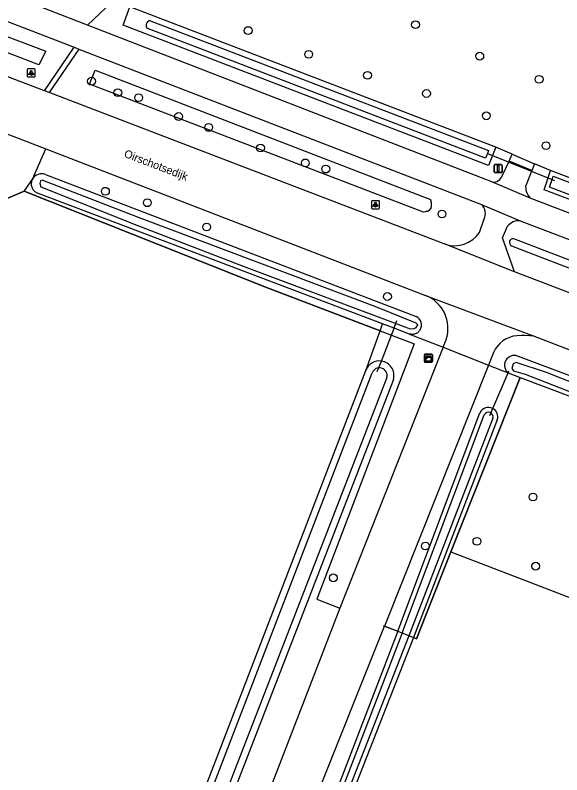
# Model space of a CAD drawing. Extents: x 155209 to 156823, y 385356 to 388482.
# Drawn here: x 155814.6 to 155882.9, y 386615.6 to 386710.5 of the extents above; entities that cross this region are included whole.
import ezdxf

# ---------------------------------------------------------------- set-up
doc = ezdxf.new("R2010")
doc.units = 0
for name, color, linetype in [('IMGEO_Berm_groen', 7, 'Continuous'), ('IMGEO_Boom', 7, 'Continuous'), ('IMGEO_Bouwland', 7, 'Continuous'), ('IMGEO_Duiker', 7, 'Continuous'), ('IMGEO_Erf', 7, 'Continuous'), ('IMGEO_Fietspad_gesloten', 7, 'Continuous'), ('IMGEO_Gemengd_bos', 7, 'Continuous'), ('IMGEO_Grasland_overig', 7, 'Continuous'), ('IMGEO_Groenvoorziening', 7, 'Continuous'), ('IMGEO_Haag', 7, 'Continuous'), ('IMGEO_Hek', 7, 'Continuous'), ('IMGEO_Kast', 7, 'Continuous'), ('IMGEO_Lichtpunt', 7, 'Continuous'), ('IMGEO_Openbare_ruimte_label', 7, 'Continuous'), ('IMGEO_Rijbaan_lokaal_gesloten', 7, 'Continuous'), ('IMGEO_Rijbaan_lokaal_open', 7, 'Continuous'), ('IMGEO_Verkeersbordpaal', 7, 'Continuous'), ('IMGEO_Voetpad_gesloten', 7, 'Continuous'), ('IMGEO_Voetpad_open', 7, 'Continuous'), ('IMGEO_Waterloop', 7, 'Continuous')]:
    doc.layers.add(name, color=color, linetype=linetype)

msp = doc.modelspace()

# ---------------------------------------------------------------- linework, layer by layer
at = {"layer": 'IMGEO_Berm_groen'}
for points in [[(155823.665, 386709.227), (155826.778, 386712.153)], [(155874.621, 386693.991), (155873.73, 386691.681), (155828.114, 386709.2), (155828.929, 386711.51)], [(155876.68, 386693.108), (155874.621, 386693.991)], [(155881.467, 386691.056), (155879.459, 386691.917)], [(155990.993, 386649.297), (155990.059, 386646.729), (155916.515, 386675.029), (155880.657, 386688.651), (155881.467, 386691.056)]]:
    msp.add_lwpolyline(points, dxfattribs=at)
at = {"layer": 'IMGEO_Boom'}
for centre in [(155864.597, 386709.277), (155843.706, 386708.537), (155851.258, 386705.57), (155872.619, 386705.348), (155858.612, 386702.951), (155824.146, 386702.213), (155880.027, 386702.457), (155827.432, 386700.793), (155830.038, 386700.161), (155865.97, 386700.682), (155873.443, 386697.898), (155835.012, 386697.815), (155838.779, 386696.449), (155880.893, 386694.173), (155845.249, 386693.882), (155850.838, 386692.012), (155853.394, 386691.245), (155825.883, 386688.476), (155831.122, 386687.042), (155867.902, 386685.635), (155838.526, 386684.007), (155861.097, 386675.328), (155879.268, 386650.298), (155865.821, 386644.183), (155872.268, 386644.761), (155879.594, 386641.667), (155854.345, 386640.206)]:
    msp.add_circle(centre, 0.489, dxfattribs=at)
at = {"layer": 'IMGEO_Bouwland'}
for points in [[(155877.654, 386665.232), (155902.971, 386655.706), (155974.965, 386627.941)], [(155869.012, 386643.444), (155965.818, 386606.23)], [(155864.342, 386632.757), (155844.679, 386582.556)]]:
    msp.add_lwpolyline(points, dxfattribs=at)
at = {"layer": 'IMGEO_Duiker'}
for points in [[(155873.596, 386693.18), (155881.972, 386689.814)], [(155859.832, 386665.968), (155860.333, 386667.272), (155861.916, 386671.386), (155862.286, 386672.347)], [(155873.863, 386660.477), (155874.243, 386661.361), (155876.162, 386665.818), (155876.265, 386666.058)]]:
    msp.add_lwpolyline(points, dxfattribs=at)
at = {"layer": 'IMGEO_Erf'}
msp.add_lwpolyline([(155832.483, 386598.7), (155858.387, 386666.091)], dxfattribs=at)
at = {"layer": 'IMGEO_Fietspad_gesloten'}
for points in [[(155823.665, 386709.227), (155792.559, 386721.3), (155782.523, 386725.195)], [(155783.255, 386721.411), (155791.391, 386718.27), (155821.976, 386706.464)], [(155874.108, 386689.649), (155823.665, 386709.227)], [(155821.976, 386706.464), (155822.578, 386706.232)], [(155822.578, 386706.232), (155872.835, 386686.832)], [(155878.92, 386687.627), (155874.108, 386689.649)], [(156159.448, 386578.782), (156158.601, 386579.012), (156156.646, 386579.821), (156152.282, 386581.927), (156148.252, 386583.662), (156143.989, 386585.35), (156138.311, 386587.803), (156129.225, 386591.346), (156120.939, 386594.792), (156119.186, 386595.665), (156114.697, 386597.381), (156053.616, 386620.734), (156000, 386641.233), (155995.683, 386642.884), (155990.492, 386644.876), (155878.92, 386687.627)], [(155872.835, 386686.832), (155877.683, 386684.795)], [(155877.683, 386684.795), (155916.39, 386670.002), (155989.461, 386642.004)]]:
    msp.add_lwpolyline(points, dxfattribs=at)
at = {"layer": 'IMGEO_Gemengd_bos'}
for points in [[(155874.621, 386693.991), (155828.929, 386711.51)], [(155990.993, 386649.297), (155881.467, 386691.056)]]:
    msp.add_lwpolyline(points, dxfattribs=at)
at = {"layer": 'IMGEO_Grasland_overig'}
msp.add_lwpolyline([(155862.382, 386633.537), (155843.124, 386583.393)], dxfattribs=at)
at = {"layer": 'IMGEO_Groenvoorziening'}
for points in [[(155860.498, 386671.922), (155817.385, 386688.232), (155817.29, 386688.282), (155817.193, 386688.344), (155817.103, 386688.414), (155817.019, 386688.492), (155816.943, 386688.578), (155816.874, 386688.669), (155816.814, 386688.767), (155816.763, 386688.869), (155816.721, 386688.976), (155816.689, 386689.086), (155816.667, 386689.198), (155816.655, 386689.312), (155816.653, 386689.426), (155816.662, 386689.54), (155816.68, 386689.653), (155816.709, 386689.764), (155816.747, 386689.872), (155816.795, 386689.976)], [(155818.383, 386690.586), (155864.671, 386672.831)], [(155860.167, 386671.061), (155845.778, 386676.556), (155815.753, 386688.468)], [(155858.387, 386666.091), (155860.167, 386671.061)], [(155865.168, 386671.155), (155865.139, 386671.111), (155865.076, 386671.028), (155865.006, 386670.951), (155864.93, 386670.88), (155864.847, 386670.817), (155864.759, 386670.761), (155864.667, 386670.713), (155864.57, 386670.674), (155864.471, 386670.643), (155864.369, 386670.622), (155864.265, 386670.61), (155864.161, 386670.606), (155864.057, 386670.613), (155863.954, 386670.628), (155863.853, 386670.653)], [(155875.801, 386667.204), (155875.766, 386667.101), (155875.74, 386666.995), (155875.724, 386666.888), (155875.717, 386666.779), (155875.72, 386666.671), (155875.733, 386666.562), (155875.755, 386666.456), (155875.787, 386666.352), (155875.828, 386666.251), (155875.877, 386666.154), (155875.936, 386666.063), (155876.002, 386665.976), (155876.075, 386665.896), (155876.162, 386665.818)], [(156034.045, 386607.743), (156000, 386620.965), (155902.837, 386658.33), (155877.112, 386667.965)], [(155861.841, 386664.972), (155835.62, 386597.315)]]:
    msp.add_lwpolyline(points, dxfattribs=at)
for centre, radius, start, end in [((155817.932, 386689.388), 1.28, 69.36476, 152.6619), ((155864.178, 386671.773), 1.167, 328.01445, 65.01988), ((155860.095, 386665.471), 1.817, 82.46184, 160.04411), ((155860.093, 386665.47), 1.818, 344.08825, 82.41363), ((155876.936, 386666.758), 1.219, 81.70738, 158.56063)]:
    msp.add_arc(centre, radius, start, end, dxfattribs=at)
at = {"layer": 'IMGEO_Haag'}
for points in [[(155860.167, 386671.061), (155860.498, 386671.922)], [(155863.853, 386670.653), (155861.916, 386671.386), (155860.498, 386671.922)], [(155860.167, 386671.061), (155864.421, 386669.436), (155852.275, 386637.556), (155855.141, 386636.416)], [(155863.853, 386670.653), (155868.05, 386669.004)], [(155873.724, 386666.776), (155876.162, 386665.818)], [(155877.654, 386665.232), (155869.012, 386643.444)], [(155876.162, 386665.818), (155877.654, 386665.232)], [(155862.382, 386633.537), (155872.635, 386660.799)], [(155874.811, 386659.93), (155864.342, 386632.757)], [(155869.012, 386643.444), (155864.715, 386632.609), (155864.342, 386632.757)], [(155860.743, 386634.189), (155862.382, 386633.537)]]:
    msp.add_lwpolyline(points, dxfattribs=at)
for centre, radius, start, end in [((155873.705, 386660.319), 1.173, 62.69286, 155.83644), ((155873.706, 386660.32), 1.172, 340.5752, 62.72356)]:
    msp.add_arc(centre, radius, start, end, dxfattribs=at)
at = {"layer": 'IMGEO_Hek'}
for points in [[(155807.945, 386691.605), (155808.555, 386689.616), (155811.529, 386686.692), (155815.753, 386688.468)], [(155815.753, 386688.468), (155845.778, 386676.556), (155860.167, 386671.061)], [(155864.342, 386632.757), (155864.715, 386632.609), (155869.012, 386643.444), (155877.654, 386665.232)], [(155860.542, 386634.269), (155862.382, 386633.537)], [(155862.382, 386633.537), (155864.342, 386632.757)]]:
    msp.add_lwpolyline(points, dxfattribs=at)
at = {"layer": 'IMGEO_Kast'}
for p, q in [((155865.701, 386667.208), (155865.701, 386668.049)), ((155865.701, 386668.049), (155865.701, 386667.208)), ((155865.776, 386668.133), (155866.617, 386668.133)), ((155866.617, 386668.133), (155865.776, 386668.133)), ((155866.701, 386668.058), (155866.701, 386667.217)), ((155866.701, 386667.217), (155866.701, 386668.058)), ((155866.626, 386667.133), (155865.785, 386667.133)), ((155865.785, 386667.133), (155866.626, 386667.133))]:
    msp.add_line(p, q, dxfattribs=at)
for points in [[(155865.896, 386667.923), (155866.496, 386667.923), (155866.496, 386667.838), (155865.896, 386667.838), (155865.896, 386667.923)], [(155865.896, 386667.748), (155866.496, 386667.748), (155866.496, 386667.259), (155865.896, 386667.259), (155865.896, 386667.748)]]:
    msp.add_lwpolyline(points, dxfattribs=at)
msp.add_circle((155865.98, 386667.597), 0.0377, dxfattribs=at)
for centre, start, end in [((155865.779, 386668.055), 92.4484, 184.28452), ((155865.779, 386668.055), 92.4484, 184.28452), ((155866.623, 386668.055), 2.4484, 94.28452), ((155866.623, 386668.055), 2.4484, 94.28452), ((155865.779, 386667.211), 182.4484, 274.28452), ((155865.779, 386667.211), 182.4484, 274.28452), ((155866.623, 386667.211), 272.4484, 4.28452), ((155866.623, 386667.211), 272.4484, 4.28452)]:
    msp.add_arc(centre, 0.0779, start, end, dxfattribs=at)
at = {"layer": 'IMGEO_Lichtpunt'}
for p, q in [((155816.118, 386703.647), (155816.118, 386702.84)), ((155816.118, 386703.647), (155816.118, 386702.84)), ((155817.02, 386703.742), (155816.212, 386703.742)), ((155817.02, 386703.742), (155816.212, 386703.742)), ((155817.114, 386702.84), (155817.114, 386703.647)), ((155817.114, 386702.84), (155817.114, 386703.647)), ((155816.212, 386702.746), (155817.02, 386702.746)), ((155816.212, 386702.746), (155817.02, 386702.746)), ((155859.099, 386687.2), (155859.099, 386686.393)), ((155859.099, 386687.2), (155859.099, 386686.393)), ((155860.001, 386687.295), (155859.193, 386687.295)), ((155860.001, 386687.295), (155859.193, 386687.295)), ((155860.095, 386686.393), (155860.095, 386687.2)), ((155860.095, 386686.393), (155860.095, 386687.2)), ((155859.193, 386686.299), (155860.001, 386686.299)), ((155859.193, 386686.299), (155860.001, 386686.299))]:
    msp.add_line(p, q, dxfattribs=at)
for points in [[(155816.492, 386703.311), (155816.531, 386703.283), (155816.343, 386703.021), (155816.305, 386703.048), (155816.492, 386703.311)], [(155816.594, 386703.263), (155816.641, 386703.263), (155816.641, 386702.941), (155816.594, 386702.941), (155816.594, 386703.263)], [(155816.704, 386703.283), (155816.742, 386703.31), (155816.929, 386703.048), (155816.89, 386703.02), (155816.704, 386703.283)], [(155859.473, 386686.864), (155859.512, 386686.836), (155859.324, 386686.574), (155859.286, 386686.601), (155859.473, 386686.864)], [(155859.575, 386686.816), (155859.622, 386686.816), (155859.622, 386686.494), (155859.575, 386686.494), (155859.575, 386686.816)], [(155859.685, 386686.836), (155859.723, 386686.863), (155859.91, 386686.601), (155859.871, 386686.573), (155859.685, 386686.836)]]:
    msp.add_lwpolyline(points, dxfattribs=at)
for centre in [(155816.617, 386703.445), (155859.598, 386686.998)]:
    msp.add_circle(centre, 0.0994, dxfattribs=at)
for centre, start, end in [((155816.212, 386703.647), 90, 180), ((155816.212, 386703.647), 90, 180), ((155817.02, 386703.647), 0, 90), ((155817.02, 386703.647), 0, 90), ((155816.212, 386702.84), 180, 270), ((155816.212, 386702.84), 180, 270), ((155817.02, 386702.84), 270, 0), ((155817.02, 386702.84), 270, 360), ((155859.193, 386687.2), 90, 180), ((155859.193, 386687.2), 90, 180), ((155860.001, 386687.2), 0, 90), ((155860.001, 386687.2), 0, 90), ((155859.193, 386686.393), 180, 270), ((155859.193, 386686.393), 180, 270), ((155860.001, 386686.393), 270, 0), ((155860.001, 386686.393), 270, 360)]:
    msp.add_arc(centre, 0.0946, start, end, dxfattribs=at)
at = {"layer": 'IMGEO_Rijbaan_lokaal_gesloten'}
for points in [[(155818.26, 386701.023), (155787.542, 386712.8)], [(155818.862, 386700.793), (155818.26, 386701.023)], [(155868.311, 386681.855), (155868.044, 386681.961), (155867.852, 386682.037), (155818.862, 386700.793)], [(155810.968, 386696.648), (155818.432, 386693.767)], [(155818.432, 386693.767), (155865.843, 386675.465)], [(155876.97, 386678.422), (155868.311, 386681.855)], [(155985.416, 386636.888), (155984.595, 386637.217), (155876.97, 386678.422)], [(155865.843, 386675.465), (155879.407, 386670.403)], [(155879.407, 386670.403), (156000, 386623.973), (156047.624, 386605.618), (156122.657, 386576.842), (156130.329, 386573.936), (156139.465, 386570.312)]]:
    msp.add_lwpolyline(points, dxfattribs=at)
at = {"layer": 'IMGEO_Rijbaan_lokaal_open'}
for points in [[(155868.05, 386669.004), (155868.423, 386669.945)], [(155879.407, 386670.403), (155878.869, 386670.437), (155878.193, 386670.466), (155877.791, 386670.469), (155877.252, 386670.439)], [(155868.05, 386669.004), (155867.808, 386668.392), (155855.141, 386636.416)], [(155868.05, 386669.004), (155873.724, 386666.776)], [(155874.34, 386668.323), (155873.724, 386666.776)], [(155873.724, 386666.776), (155860.743, 386634.189)], [(155855.141, 386636.416), (155840.588, 386598.693), (155839.455, 386597.184), (155836.897, 386595.988), (155834.967, 386595.485), (155833.269, 386595.024), (155831.102, 386595.084)], [(155837.236, 386577.022), (155842.995, 386589.803), (155860.743, 386634.189)]]:
    msp.add_lwpolyline(points, dxfattribs=at)
for centre, radius, start, end in [((155864.25, 386671.357), 4.406, 341.30327, 68.79868), ((155877.565, 386666.947), 3.506, 95.11832, 156.88961)]:
    msp.add_arc(centre, radius, start, end, dxfattribs=at)
at = {"layer": 'IMGEO_Verkeersbordpaal'}
for p, q in [((155874.512, 386691.798), (155875.302, 386691.798)), ((155875.302, 386691.798), (155874.512, 386691.798)), ((155874.412, 386690.898), (155874.412, 386691.698)), ((155874.412, 386691.698), (155874.412, 386690.898)), ((155875.302, 386690.798), (155874.512, 386690.798)), ((155874.512, 386690.798), (155875.302, 386690.798)), ((155875.402, 386691.698), (155875.402, 386690.898)), ((155875.402, 386690.898), (155875.402, 386691.698))]:
    msp.add_line(p, q, dxfattribs=at)
msp.add_lwpolyline([(155874.832, 386691.673), (155874.982, 386691.673), (155874.982, 386690.923), (155874.832, 386690.923), (155874.832, 386691.673)], dxfattribs=at)
for centre, start, end in [((155874.512, 386691.698), 90, 180), ((155874.512, 386691.698), 90, 180), ((155875.302, 386691.698), 0, 90), ((155875.302, 386691.698), 360, 90), ((155874.512, 386690.898), 180, 270), ((155874.512, 386690.898), 180, 270), ((155875.302, 386690.898), 270, 0), ((155875.302, 386690.898), 270, 0)]:
    msp.add_arc(centre, 0.1, start, end, dxfattribs=at)
at = {"layer": 'IMGEO_Voetpad_gesloten'}
for points in [[(155816.795, 386689.976), (155818.432, 386693.767)], [(155815.753, 386688.468), (155811.529, 386686.692), (155808.555, 386689.616), (155807.945, 386691.605)], [(155815.753, 386688.468), (155815.983, 386688.8), (155816.795, 386689.976)]]:
    msp.add_lwpolyline(points, dxfattribs=at)
at = {"layer": 'IMGEO_Voetpad_open'}
for points in [[(155818.26, 386701.023), (155821.976, 386706.464)], [(155822.578, 386706.232), (155818.862, 386700.793)], [(155876.272, 386692.223), (155876.68, 386693.108)], [(155876.68, 386693.108), (155879.459, 386691.917)], [(155875.468, 386690.478), (155876.272, 386692.223)], [(155879.131, 386691.078), (155876.272, 386692.223)], [(155879.459, 386691.917), (155879.131, 386691.078)], [(155879.131, 386691.078), (155878.349, 386689.08)], [(155872.577, 386683.328), (155873.163, 386685.028)], [(155876.97, 386678.422), (155875.473, 386682.662), (155876.083, 386684.111)]]:
    msp.add_lwpolyline(points, dxfattribs=at)
for centre, radius, start, end in [((155874.312, 386690.845), 1.213, 260.33528, 342.39425), ((155880.374, 386689.037), 2.026, 178.78705, 224.12063), ((155871.798, 386685.712), 1.526, 333.39135, 47.21834), ((155877.521, 386682.962), 1.841, 84.93592, 141.3575), ((155869.463, 386685.432), 3.758, 252.15024, 325.94815)]:
    msp.add_arc(centre, radius, start, end, dxfattribs=at)
at = {"layer": 'IMGEO_Waterloop'}
for points in [[(155785.566, 386717.88), (155790.567, 386716.128), (155803.207, 386711.701), (155818.456, 386705.974), (155817.551, 386704.278), (155803.725, 386709.57), (155789.982, 386714.61), (155785.106, 386716.398)], [(155831.388, 386709.803), (155873.698, 386693.581), (155873.596, 386693.18), (155873.321, 386692.603), (155831.054, 386708.835)], [(155823.911, 386701.844), (155824.608, 386703.598), (155866.464, 386687.429), (155866.53, 386687.24)], [(155866.016, 386685.972), (155865.813, 386685.924), (155865.6, 386685.886), (155823.911, 386701.844)], [(155829.998, 386685.19), (155818.002, 386689.879), (155817.781, 386689.76), (155817.704, 386689.454), (155817.809, 386689.035), (155829.79, 386684.23), (155843.088, 386679.115), (155863.922, 386671.313), (155864.45, 386671.321), (155864.695, 386671.473), (155864.871, 386671.781), (155864.661, 386672.025), (155859.633, 386674.026), (155829.998, 386685.19)], [(155990.099, 386648.411), (155989.741, 386647.426), (155916.707, 386675.53), (155881.331, 386688.969), (155881.658, 386689.94), (155881.797, 386690.356), (155990.308, 386648.984), (155990.099, 386648.411)], [(155866.57, 386686.46), (155866.443, 386686.222)], [(155876.578, 386681.663), (155986.902, 386639.254), (155987.281, 386640.17), (155876.878, 386682.53)], [(155978.553, 386628.296), (155962.66, 386634.352), (155928.335, 386647.563), (155899.453, 386658.524), (155880.959, 386665.86), (155877.147, 386667.079), (155876.803, 386666.934), (155876.639, 386666.354), (155876.85, 386666.069), (155878.291, 386665.621), (155896.949, 386658.346), (155928.657, 386646.455), (155948.06, 386638.911), (155977.427, 386627.529), (155994.436, 386621.242), (156023.951, 386609.904), (156033.205, 386606.533), (156033.456, 386606.834), (156033.426, 386607.179), (156025.495, 386610.282), (155998.677, 386620.598), (155978.553, 386628.296)], [(155833.28, 386598.397), (155859.186, 386665.794)], [(155861.03, 386665.238), (155834.843, 386597.67)], [(155843.669, 386583.144), (155862.915, 386633.258), (155862.925, 386633.276), (155862.934, 386633.295), (155862.943, 386633.314), (155862.975, 386633.391), (155863.003, 386633.469), (155863.026, 386633.55), (155873.187, 386660.568)], [(155874.249, 386660.136), (155863.786, 386632.978), (155844.152, 386582.851)]]:
    msp.add_lwpolyline(points, dxfattribs=at)
for centre, radius, start, end in [((155831.679, 386709.133), 0.73, 113.50821, 162.99117), ((155831.742, 386709.194), 0.776, 168.65874, 207.57013), ((155865.378, 386686.79), 1.237, 344.52643, 21.34492), ((155865.841, 386686.761), 0.808, 282.51832, 318.17793), ((155876.792, 386682.074), 0.464, 79.33754, 242.48909), ((155860.094, 386665.47), 0.964, 346.05589, 160.38605), ((155873.706, 386660.324), 0.574, 340.93163, 154.79739)]:
    msp.add_arc(centre, radius, start, end, dxfattribs=at)

# ---------------------------------------------------------------- texts
at = {"layer": 'IMGEO_Openbare_ruimte_label'}
msp.add_text('Oirschotsedijk', height=1, rotation=339.02829, dxfattribs=at).set_placement((155828.116, 386692.791))

doc.saveas('drawing.dxf')
